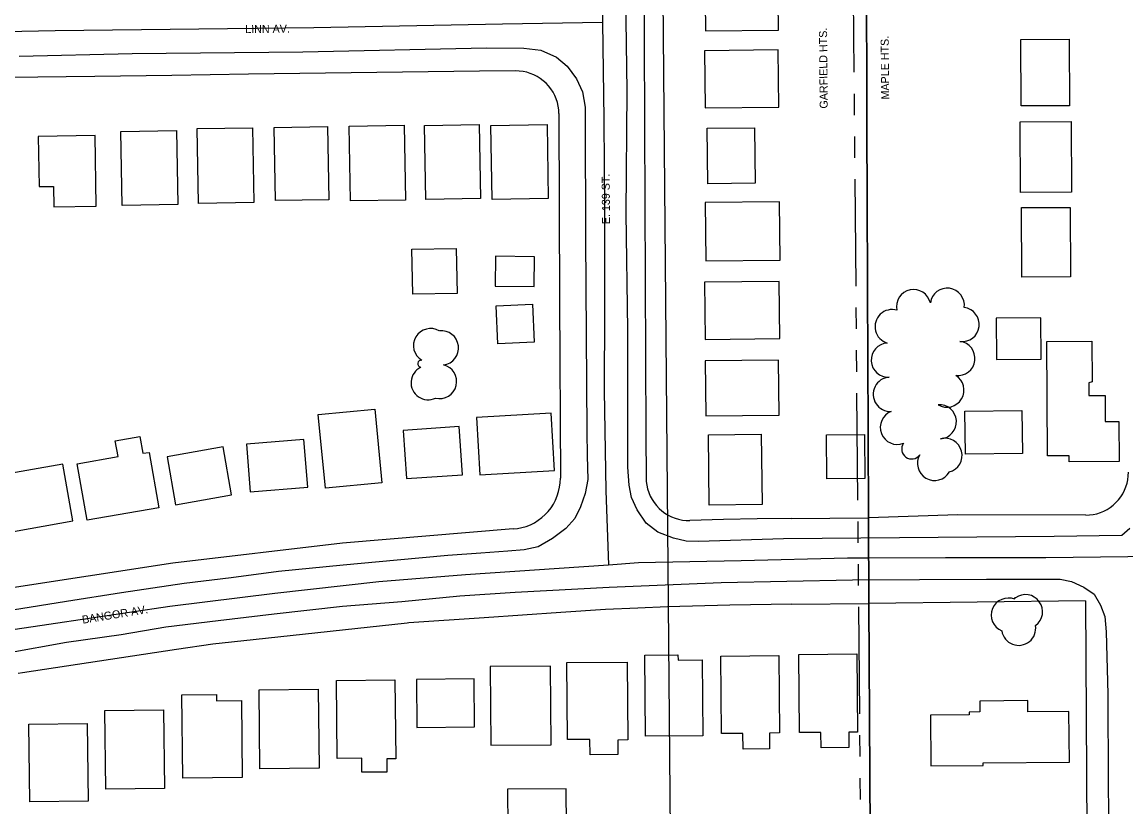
# Model space of a CAD drawing. Extents: x -2233 to 187241, y 4582 to 150524.
# Drawn here: x 115627 to 116272, y 58418 to 58877 of the extents above; entities that cross this region are included whole.
import ezdxf

# ---------------------------------------------------------------- set-up
doc = ezdxf.new("R2010")
doc.units = 0
for name, color, linetype in [('BLDG', 7, 'Continuous'), ('DIVISIONS', 7, 'Continuous'), ('DV_X_Corp_Line', 7, 'Continuous'), ('GE_X_CL_2000', 7, 'Continuous'), ('GRID', 7, 'Continuous'), ('ROAD', 7, 'Continuous'), ('ROAD-NAME', 7, 'Continuous'), ('RW_X_Fee_RW', 7, 'Continuous'), ('TREES', 7, 'Continuous')]:
    doc.layers.add(name, color=color, linetype=linetype)

msp = doc.modelspace()

# ---------------------------------------------------------------- linework, layer by layer
at = {"layer": 'BLDG'}
for points in [[(116026.35, 58871.61), (116069.05, 58872.09), (116068.66, 58906.36), (116025.96, 58905.87)], [(116238.89, 58866.7), (116239.11, 58827.87), (116210.93, 58827.71), (116210.71, 58866.55)], [(116026.18, 58826.61), (116069.17, 58827.1), (116068.8, 58860.48), (116025.8, 58859.99)], [(115716.94, 58813.29), (115717.67, 58770.08), (115685.11, 58769.53), (115684.37, 58812.74)], [(115761.47, 58815.01), (115762.22, 58771.34), (115729.87, 58770.79), (115729.12, 58814.46)], [(115805.23, 58815.73), (115805.95, 58772.9), (115774.85, 58772.37), (115774.12, 58815.19)], [(115850.06, 58816.52), (115850.81, 58772.71), (115818.67, 58772.17), (115817.93, 58815.97)], [(115893.93, 58816.79), (115894.67, 58773.58), (115862.79, 58773.05), (115862.06, 58816.25)], [(115933.64, 58816.87), (115934.38, 58773.66), (115901.59, 58773.1), (115900.85, 58816.31)], [(116055, 58815), (116055.36, 58782.56), (116027.65, 58782.24), (116027.29, 58814.69)], [(116240.16, 58818.67), (116240.39, 58777.39), (116210.57, 58777.22), (116210.33, 58818.5)], [(115636.62, 58780.55), (115645.1, 58780.7), (115645.3, 58768.66), (115670.03, 58769.08), (115669.33, 58810.37), (115636.11, 58809.8)], [(116026.55, 58737.17), (116070.01, 58737.66), (116069.63, 58771.74), (116026.18, 58771.25)], [(116239.56, 58768.44), (116239.78, 58727.76), (116211.3, 58727.61), (116211.08, 58768.29)], [(115880.57, 58744.38), (115881.01, 58718.18), (115855.07, 58717.75), (115854.62, 58743.94)], [(115903.28, 58722.42), (115926.18, 58722.14), (115926.4, 58739.54), (115903.5, 58739.82)], [(116026.14, 58691.27), (116069.85, 58691.77), (116069.47, 58725.18), (116025.76, 58724.69)], [(115925.1, 58711.89), (115926.06, 58689.65), (115904.92, 58688.74), (115903.96, 58710.97)], [(116222.62, 58679.73), (116222.34, 58703.88), (116196.2, 58703.59), (116196.48, 58679.43)], [(116252.3, 58690.25), (116252.44, 58666.47), (116250.45, 58665.93), (116250.5, 58658.45), (116260.02, 58658.52), (116260.1, 58643.31), (116268.08, 58643.35), (116268.21, 58619.83), (116239, 58619.66), (116238.98, 58623.25), (116226.3, 58623.18), (116225.92, 58690.1)], [(116026.51, 58646.56), (116069.35, 58647.04), (116068.98, 58679.17), (116026.15, 58678.69)], [(115832.92, 58650.56), (115837.09, 58607.5), (115804.01, 58604.3), (115799.84, 58647.36)], [(115894.41, 58612.08), (115938.02, 58614.61), (115936.07, 58648.23), (115892.47, 58645.7)], [(116178.05, 58649.4), (116211.32, 58649.78), (116211.6, 58624.58), (116178.33, 58624.2)], [(115851.37, 58609.91), (115884.3, 58612.2), (115882.34, 58640.34), (115849.41, 58638.05)], [(115682.77, 58622.77), (115681.16, 58631.96), (115695.58, 58634.49), (115697.3, 58624.78), (115701.01, 58625.23), (115706.67, 58592.91), (115664.69, 58585.54), (115658.89, 58618.58)], [(115760.06, 58602.14), (115793.71, 58604.87), (115791.45, 58632.72), (115757.8, 58629.99)], [(116058.94, 58635.93), (116059.4, 58594.69), (116028.54, 58594.35), (116028.08, 58635.58)], [(116119.27, 58635.73), (116119.57, 58610.04), (116097.27, 58609.79), (116096.97, 58635.48)], [(115716.42, 58594.57), (115749.19, 58600.32), (115744.25, 58628.44), (115711.48, 58622.69)], [(115614.04, 58577.71), (115656.35, 58585.13), (115650.54, 58618.26), (115608.22, 58610.84)], [(116010.2, 58506.85), (116010.23, 58503.77), (116024.36, 58503.9), (116024.75, 58459.62), (115991.25, 58459.32), (115990.83, 58506.68)], [(116069.23, 58506.51), (116069.62, 58461.21), (116063.66, 58461.16), (116063.74, 58451.99), (116048.3, 58451.85), (116048.22, 58460.99), (116035.67, 58460.88), (116035.28, 58506.21)], [(116114.73, 58507.41), (116115.13, 58461.76), (116110.03, 58461.71), (116110.11, 58452.74), (116093.92, 58452.6), (116093.84, 58461.55), (116081.23, 58461.44), (116080.83, 58507.12)], [(115936.03, 58454.35), (115935.63, 58500.31), (115900.37, 58500), (115900.77, 58454.05)], [(115980.55, 58502.66), (115980.95, 58457.13), (115975.03, 58457.08), (115975.1, 58448.55), (115958.8, 58448.41), (115958.72, 58457.43), (115945.6, 58457.32), (115945.21, 58502.35)], [(115844.67, 58492.28), (115845.18, 58446.2), (115839.88, 58446.14), (115839.96, 58438.4), (115825.41, 58438.25), (115825.32, 58446.47), (115810.95, 58446.31), (115810.46, 58491.91)], [(115857.49, 58464.43), (115891.19, 58464.72), (115890.94, 58492.79), (115857.24, 58492.5)], [(115740.28, 58483.77), (115740.33, 58479.99), (115754.89, 58480.15), (115755.38, 58435.12), (115720.59, 58434.74), (115720.07, 58483.55)], [(115799.83, 58486.78), (115800.33, 58440.62), (115765.69, 58440.25), (115765.2, 58486.4)], [(116238.82, 58473.85), (116214.9, 58473.64), (116214.84, 58480.13), (116186.74, 58479.88), (116186.8, 58473.5), (116180.45, 58473.45), (116180.47, 58471.79), (116157.83, 58471.59), (116158.08, 58441.93), (116188.78, 58442.2), (116188.77, 58443.78), (116239.08, 58444.22)], [(115709.38, 58474.71), (115709.87, 58428.68), (115675.56, 58428.3), (115675.05, 58474.33)], [(115664.75, 58466.69), (115665.24, 58421.35), (115631.1, 58420.98), (115630.6, 58466.32)], [(115910.44, 58428.3), (115910.64, 58405.68), (115922.89, 58405.79), (115923.08, 58384.4), (115945.18, 58384.59), (115944.79, 58428.6)]]:
    msp.add_lwpolyline(points, close=True, dxfattribs=at)
at = {"layer": 'DIVISIONS'}
for p, q in [((116113.25, 58847.38), (116112.71, 58909.88)), ((116113.47, 58822.39), (116113.36, 58834.88)), ((116113.69, 58797.39), (116113.58, 58809.89)), ((116114.35, 58722.39), (116113.8, 58784.89)), ((116114.56, 58697.39), (116114.45, 58709.89)), ((116114.78, 58672.39), (116114.67, 58684.89)), ((116115.44, 58597.39), (116114.89, 58659.89)), ((116115.65, 58572.39), (116115.55, 58584.89)), ((116115.87, 58547.4), (116115.76, 58559.9)), ((116116.53, 58472.4), (116115.98, 58534.9)), ((116116.75, 58447.4), (116116.64, 58459.9)), ((116116.96, 58422.4), (116116.85, 58434.9))]:
    msp.add_line(p, q, dxfattribs=at)
at = {"layer": 'DV_X_Corp_Line'}
for p, q in [((116120.32, 58905.98), (116120.52, 58868.74)), ((116120.32, 58905.98), (116120.52, 58868.74)), ((116120.52, 58868.74), (116120.32, 58905.98)), ((116120.52, 58868.74), (116120.32, 58905.98)), ((116120.52, 58868.74), (116120.56, 58860.98)), ((116120.52, 58868.74), (116120.56, 58860.98)), ((116120.56, 58860.98), (116120.52, 58868.74)), ((116120.56, 58860.98), (116120.52, 58868.74)), ((116120.56, 58860.98), (116120.73, 58828.29)), ((116120.56, 58860.98), (116120.73, 58828.29)), ((116120.73, 58828.29), (116120.56, 58860.98)), ((116120.73, 58828.29), (116120.56, 58860.98)), ((116120.73, 58828.29), (116120.75, 58823.29)), ((116120.73, 58828.29), (116120.75, 58823.29)), ((116120.75, 58823.29), (116120.73, 58828.29)), ((116120.75, 58823.29), (116120.73, 58828.29)), ((116120.75, 58823.29), (116120.66, 58818.74)), ((116120.75, 58823.29), (116120.66, 58818.74)), ((116120.66, 58818.74), (116120.75, 58823.29)), ((116120.66, 58818.74), (116120.75, 58823.29)), ((116120.66, 58818.74), (116120.62, 58816.98)), ((116120.66, 58818.74), (116120.62, 58816.98)), ((116120.62, 58816.98), (116120.66, 58818.74)), ((116120.62, 58816.98), (116120.66, 58818.74)), ((116120.62, 58816.98), (116120.63, 58815.98)), ((116120.62, 58816.98), (116120.63, 58815.98)), ((116120.63, 58815.98), (116120.62, 58816.98)), ((116120.63, 58815.98), (116120.62, 58816.98)), ((116120.63, 58815.98), (116120.81, 58771.98)), ((116120.63, 58815.98), (116120.81, 58771.98)), ((116120.81, 58771.98), (116120.63, 58815.98)), ((116120.81, 58771.98), (116120.63, 58815.98)), ((116120.81, 58771.98), (116120.81, 58770.98)), ((116120.81, 58771.98), (116120.81, 58770.98)), ((116120.81, 58770.98), (116120.81, 58771.98)), ((116120.81, 58770.98), (116120.81, 58771.98)), ((116120.81, 58770.98), (116120.82, 58768.74)), ((116120.81, 58770.98), (116120.82, 58768.74)), ((116120.82, 58768.74), (116120.81, 58770.98)), ((116120.82, 58768.74), (116120.81, 58770.98)), ((116120.82, 58768.74), (116120.99, 58726.98)), ((116120.82, 58768.74), (116120.99, 58726.98)), ((116120.99, 58726.98), (116120.82, 58768.74)), ((116120.99, 58726.98), (116120.82, 58768.74)), ((116120.99, 58726.98), (116121, 58725.98)), ((116120.99, 58726.98), (116121, 58725.98)), ((116121, 58725.98), (116120.99, 58726.98)), ((116121, 58725.98), (116120.99, 58726.98)), ((116121, 58725.98), (116121.02, 58718.74)), ((116121, 58725.98), (116121.02, 58718.74)), ((116121.02, 58718.74), (116121, 58725.98)), ((116121.02, 58718.74), (116121, 58725.98)), ((116121.02, 58718.74), (116121.17, 58681.98)), ((116121.02, 58718.74), (116121.17, 58681.98)), ((116121.17, 58681.98), (116121.02, 58718.74)), ((116121.17, 58681.98), (116121.02, 58718.74)), ((116121.17, 58681.98), (116121.18, 58680.98)), ((116121.17, 58681.98), (116121.18, 58680.98)), ((116121.18, 58680.98), (116121.17, 58681.98)), ((116121.18, 58680.98), (116121.17, 58681.98)), ((116121.18, 58680.98), (116121.36, 58636.99)), ((116121.18, 58680.98), (116121.36, 58636.99)), ((116121.36, 58636.99), (116121.18, 58680.98)), ((116121.36, 58636.99), (116121.18, 58680.98)), ((116121.36, 58636.99), (116121.36, 58635.99)), ((116121.36, 58636.99), (116121.36, 58635.99)), ((116121.36, 58635.99), (116121.36, 58636.99)), ((116121.36, 58635.99), (116121.36, 58636.99)), ((116121.36, 58635.99), (116121.56, 58586.99)), ((116121.36, 58635.99), (116121.56, 58586.99)), ((116121.56, 58586.99), (116121.36, 58635.99)), ((116121.56, 58586.99), (116121.36, 58635.99)), ((116121.56, 58586.99), (116121.8, 58536.99)), ((116121.56, 58586.99), (116121.8, 58536.99)), ((116121.8, 58536.99), (116121.56, 58586.99)), ((116121.8, 58536.99), (116121.56, 58586.99)), ((116121.8, 58536.99), (116122.98, 58314.23)), ((116121.8, 58536.99), (116122.98, 58314.23)), ((116122.98, 58314.23), (116121.8, 58536.99)), ((116122.98, 58314.23), (116121.8, 58536.99))]:
    msp.add_line(p, q, dxfattribs=at)
at = {"layer": 'GE_X_CL_2000'}
for points in [[(115966.95, 59164.92), (115967.92, 59161.87), (115968.7, 59158.77), (115969.26, 59155.62), (115969.62, 59152.44), (115969.76, 59149.24), (115969.7, 59146.05), (115965.91, 59096.39), (115965.6, 59047.16), (115965.87, 58989.27), (115965.75, 58933.74), (115966.05, 58876.71)], [(115342.76, 58774.57), (115361.42, 58785.09), (115389.78, 58804.42), (115400.59, 58812.3), (115412.74, 58819.81), (115429.91, 58829.13), (115456.89, 58842.96), (115474.81, 58850.44), (115491, 58855.99), (115499.21, 58858.43), (115507.48, 58860.63), (115515.82, 58862.59), (115524.2, 58864.33), (115532.63, 58865.82), (115541.1, 58867.08), (115549.6, 58868.1), (115558.12, 58868.88), (115587.43, 58870.16), (115616.75, 58871.14), (115646.08, 58871.82), (115797.27, 58873.63), (115907.58, 58875.66), (115966.05, 58876.71)], [(115966.05, 58876.71), (115966.8, 58820.09), (115967.15, 58765.45), (115967.33, 58708.02), (115967.07, 58661.47), (115968.01, 58602.78), (115969.62, 58559.56)], [(115969.62, 58559.56), (115987.22, 58560.77), (116047.25, 58562.01), (116109.3, 58563.54), (116122.07, 58563.6)], [(116122.07, 58563.6), (116166.73, 58563.83), (116225.27, 58563.86), (116273.35, 58564.41), (116297.79, 58564.54)], [(115453.26, 58493.74), (115463.88, 58495.51), (115485.51, 58499.58), (115530.47, 58506.83), (115592.27, 58517.45), (115642.26, 58524.82), (115713.01, 58535.27), (115774.53, 58542.98), (115835.24, 58549.81), (115886.02, 58553.84), (115969.62, 58559.56)]]:
    msp.add_lwpolyline(points, dxfattribs=at)
at = {"layer": 'GRID'}
msp.add_line((115990.85, 60095.95), (116014.4, 57398.28), dxfattribs=at)
at = {"layer": 'ROAD'}
for points in [[(116274.39, 58580.76), (116269.87, 58576.57), (116230.26, 58576.13), (116071.85, 58574.79), (116022.23, 58573.05), (116015.02, 58573.25), (116007.65, 58575.07), (115998.52, 58578.65), (115991.7, 58583.85), (115986.33, 58591.63), (115983.02, 58598.95), (115981.6, 58606.03), (115980.98, 58616.54), (115980.89, 58641.01), (115980.97, 58697.08), (115979.88, 58764.81), (115980.42, 58836.58), (115979.52, 58905.43)], [(115624.97, 58856.81), (115691.12, 58858.28), (115790.76, 58859.39), (115898.16, 58861.68), (115920.13, 58861.4), (115929.95, 58860.32), (115939.08, 58856.23), (115945.46, 58850.97), (115950.95, 58843.58), (115954.39, 58835.94), (115956, 58826.99), (115955.99, 58819.79), (115956.2, 58750.63), (115956.85, 58637.17), (115957.15, 58623.14), (115957.44, 58609.38), (115955.93, 58601.24), (115953.29, 58593.43), (115949.89, 58586.55), (115944.57, 58580.73), (115936.93, 58574.93), (115928.47, 58570.05), (115920.26, 58568.31), (115910.63, 58567.52), (115894.92, 58566.29), (115875.58, 58565), (115846.03, 58562.16), (115814.36, 58559.33), (115776.56, 58555.51), (115748.83, 58551.97), (115721.47, 58548.51), (115684.79, 58543.18), (115652.68, 58538.15), (115605.16, 58530.4)], [(115618.15, 58508.1), (115652.7, 58514.31), (115684.51, 58518.84), (115710.8, 58523.3), (115741.35, 58526.96), (115774.07, 58530.78), (115814.02, 58535.36), (115848.81, 58538), (115882.62, 58541.46), (115915.04, 58543.47), (115969.93, 58546.46), (116035.52, 58549.12), (116112.25, 58550.82), (116190.6, 58551.15), (116233.8, 58551.1), (116240.3, 58549.7), (116247.49, 58546.5), (116253.62, 58542.43), (116257.24, 58535.91), (116259.86, 58529.21), (116260.59, 58520.33), (116261.6, 58483.9), (116261.84, 58432.08), (116262.39, 58378.26)]]:
    msp.add_lwpolyline(points, dxfattribs=at)
at = {"layer": 'RW_X_Fee_RW'}
for p, q in [((115990.43, 58860.45), (115990.58, 58823.47)), ((116076.31, 58586.55), (116121.56, 58586.99)), ((116076.79, 58536.56), (116121.8, 58536.99)), ((116248.43, 58538.55), (116121.8, 58536.99)), ((116248.43, 58538.55), (116250.83, 58193.85))]:
    msp.add_line(p, q, dxfattribs=at)
for points in [[(115990.16, 58924.47), (115990.24, 58906.45), (115990.24, 58905.45), (115990.37, 58873.97)], [(115990.37, 58873.97), (115990.42, 58861.45), (115990.43, 58860.45)], [(115915.22, 58848.29), (115894.13, 58848.12), (115849.13, 58847.49), (115804.14, 58846.86), (115759.14, 58846.23), (115714.14, 58845.6), (115669.15, 58844.97), (115619.15, 58844.27), (115589.92, 58843.74)], [(115940.58, 58823.26), (115940.47, 58825.46), (115940.17, 58827.63), (115939.69, 58829.77), (115939.01, 58831.86), (115938.16, 58833.88), (115937.13, 58835.82), (115935.94, 58837.66), (115934.59, 58839.39), (115933.09, 58841), (115931.46, 58842.47), (115929.71, 58843.79), (115927.84, 58844.95), (115925.89, 58845.94), (115923.85, 58846.75), (115921.75, 58847.39), (115919.6, 58847.84), (115917.42, 58848.09), (115915.22, 58848.29)], [(115940.58, 58823.26), (115941.02, 58713.76), (115941.44, 58610.07)], [(115990.58, 58823.47), (115990.6, 58816.46), (115990.61, 58815.46), (115990.79, 58771.46), (115990.79, 58770.46), (115990.97, 58726.46), (115990.98, 58725.46), (115991.15, 58681.46), (115991.16, 58680.46), (115991.34, 58636.46), (115991.34, 58635.46), (115991.52, 58610.35)], [(116248.63, 58588.55), (116250.83, 58588.65), (116252.93, 58588.95), (116255.13, 58589.35), (116257.23, 58590.05), (116259.23, 58590.85), (116261.13, 58591.85), (116263.03, 58593.05), (116264.73, 58594.35), (116266.33, 58595.85), (116267.83, 58597.45), (116269.13, 58599.25), (116270.33, 58601.05), (116271.33, 58603.05), (116272.13, 58605.05), (116272.83, 58607.15), (116273.33, 58609.25), (116273.53, 58611.45), (116273.63, 58613.65)], [(115913.81, 58580.45), (115916.42, 58580.73), (115918.99, 58581.25), (115921.51, 58582), (115923.95, 58582.96), (115926.3, 58584.14), (115928.53, 58585.52), (115930.63, 58587.09), (115932.58, 58588.84), (115934.37, 58590.76), (115935.98, 58592.83), (115937.41, 58595.04), (115938.63, 58597.36), (115939.64, 58599.78), (115940.43, 58602.29), (115941, 58604.85), (115941.34, 58607.45), (115941.44, 58610.07)], [(115991.52, 58610.35), (115991.7, 58608.22), (115991.99, 58606.02), (115992.47, 58603.85), (115993.14, 58601.74), (115994, 58599.7), (115995.04, 58597.74), (115996.24, 58595.88), (115997.61, 58594.13), (115999.12, 58592.51), (116000.77, 58591.03), (116002.55, 58589.7), (116004.44, 58588.54), (116006.42, 58587.55), (116008.48, 58586.74), (116010.61, 58586.11), (116012.78, 58585.67), (116014.99, 58585.43), (116017.2, 58585.39)], [(116248.63, 58588.55), (116173.83, 58588.67), (116121.56, 58586.99)], [(116076.31, 58586.55), (116056.61, 58586.3), (116036.9, 58585.91), (116017.2, 58585.39)], [(115913.81, 58580.45), (115814.11, 58572.16), (115714.75, 58560.45), (115615.85, 58545.31)], [(116076.79, 58536.56), (116040.47, 58535.98), (116004.16, 58534.94), (115986.78, 58534.22), (115967.87, 58533.44)], [(115967.87, 58533.44), (115941.8, 58531.66), (115896.81, 58528.6), (115852.86, 58525.6), (115851.83, 58525.49), (115806.85, 58520.59), (115761.88, 58515.7), (115738.26, 58513.13), (115716.9, 58509.92), (115671.94, 58503.17), (115626.97, 58496.43), (115624.27, 58496.02)]]:
    msp.add_lwpolyline(points, dxfattribs=at)
at = {"layer": 'TREES'}
for centre, radius, start, end in [((116148.03, 58710.44), 10, 12.20403, 192.20403), ((116167.71, 58711.22), 10, 352.35134, 172.35134), ((116176.38, 58699.97), 10, 262.83611, 82.83611), ((116135.44, 58698.73), 10, 73.64971, 253.64971), ((115865.53, 58687.64), 10, 59.17408, 239.17408), ((115871.9, 58686.3), 10, 277.12913, 97.12913), ((116133.21, 58679.15), 10, 93.33194, 273.33194), ((116173.89, 58680.12), 10, 262.85972, 82.85972), ((115860.09, 58677.01), 2.06, 81.07948, 261.07948), ((115864.1, 58665.96), 10, 115.63418, 295.63418), ((115870.78, 58666.66), 10, 256.35566, 76.35566), ((116134.37, 58659.18), 10, 93.33201, 273.33201), ((116167.48, 58661.63), 10, 238.92022, 58.92022), ((116163.05, 58643.1), 10, 274.16789, 94.16789), ((116138.52, 58639.86), 10, 110.92919, 290.92919), ((116166.33, 58623.46), 10, 284.84167, 104.84167), ((116146.84, 58627.17), 5.81, 144.83592, 324.83592), ((116160.25, 58618.81), 10, 149.88838, 329.88838), ((116213.43, 58532.08), 10, 305.98491, 125.98491), ((116203.36, 58530.1), 10, 67.62051, 247.62051), ((116207.36, 58539.76), 0.455, 64.88348, 244.88348), ((116209.43, 58522.43), 10, 189.01779, 9.01779)]:
    msp.add_arc(centre, radius, start, end, dxfattribs=at)

# ---------------------------------------------------------------- texts
at = {"layer": 'DIVISIONS'}
for s, p in [('GARFIELD HTS.', (116097.78, 58826.21)), ('MAPLE HTS.', (116133.73, 58831.51))]:
    msp.add_text(s, height=4.68, rotation=90.5, dxfattribs=at).set_placement(p)
at = {"layer": 'ROAD-NAME'}
for s, rotation, p in [('LINN AV.', 0.5, (115757.18, 58870.31)), ('E. 139 ST.', 90.5, (115970.5, 58758.64)), ('BANGOR AV.', 9.19774, (115662.14, 58525.06))]:
    msp.add_text(s, height=4.68, rotation=rotation, dxfattribs=at).set_placement(p)

doc.saveas('drawing.dxf')
